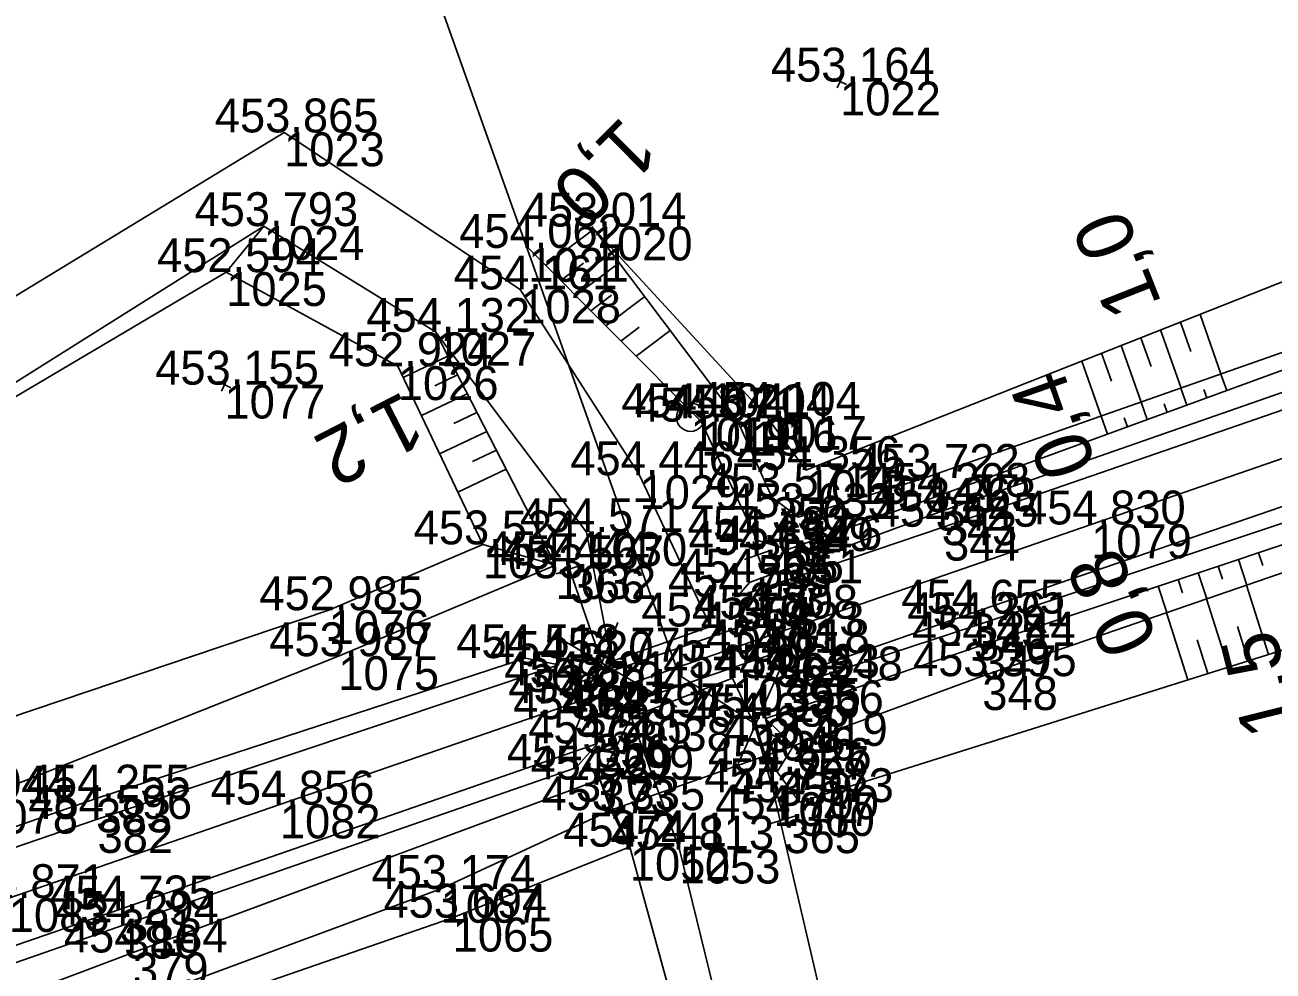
# Model space of a CAD drawing. Extents: x -751615 to -750797, y -1114905 to -1114561.
# Drawn here: x -751550.15 to -751505.91, y -1114830.9 to -1114797.38 of the extents above; entities that cross this region are included whole.
import ezdxf

# ---------------------------------------------------------------- set-up
doc = ezdxf.new("R2010")
doc.units = 0
for name, color, linetype in [('Vrstva 1', 7, 'Continuous'), ('Vrstva 19', 7, 'Continuous'), ('Vrstva 4', 7, 'Continuous'), ('Vrstva 48', 7, 'Continuous'), ('Vrstva 49', 7, 'Continuous'), ('Vrstva 51', 7, 'Continuous'), ('Vrstva 53', 7, 'Continuous'), ('Vrstva 60', 7, 'Continuous'), ('Vrstva 61', 7, 'Continuous'), ('Vrstva 7', 7, 'Continuous')]:
    doc.layers.add(name, color=color, linetype=linetype)

msp = doc.modelspace()

# ---------------------------------------------------------------- linework, layer by layer
at = {"layer": 'Vrstva 1'}
msp.add_lwpolyline([(-751416.742, -1114782.09), (-751426.633, -1114785.503), (-751435.883, -1114788.699), (-751445.473, -1114792.007), (-751455.331, -1114795.406), (-751464.93, -1114798.717), (-751474.392, -1114801.982), (-751484.022, -1114805.308), (-751487.237, -1114806.416), (-751493.406, -1114808.538), (-751502.885, -1114811.809), (-751512.358, -1114815.079), (-751523.744, -1114819.014), (-751530.663, -1114821.401), (-751541.116, -1114825.002), (-751550.726, -1114828.317), (-751560.172, -1114831.578), (-751569.853, -1114834.918), (-751579.125, -1114838.113), (-751588.602, -1114841.381)], dxfattribs=at)
at = {"layer": 'Vrstva 19'}
msp.add_line((-751529.387, -1114825.203), (-751522.915, -1114822.926), dxfattribs=at)
at = {"layer": 'Vrstva 4'}
for p, q in [((-751527.056, -1114820.157), (-751542.756, -1114776.116)), ((-751530.372, -1114816.499), (-751531.318, -1114816.825)), ((-751530.845, -1114816.662), (-751529.698, -1114819.986)), ((-751529.133, -1114818.557), (-751530.828, -1114822.844)), ((-751527.046, -1114821.54), (-751531.024, -1114819.21)), ((-751524.869, -1114823.564), (-751523.009, -1114819.347)), ((-751526.838, -1114820.502), (-751522.955, -1114822.986)), ((-751523.233, -1114825.525), (-751524.249, -1114822.158)), ((-751523.712, -1114825.669), (-751522.754, -1114825.381))]:
    msp.add_line(p, q, dxfattribs=at)
for points in [[(-751187.894, -1114700.58), (-751206.028, -1114707.041), (-751231.235, -1114715.596), (-751249.544, -1114721.971), (-751267.723, -1114728.471), (-751285.298, -1114734.541), (-751305.686, -1114741.509), (-751323.628, -1114747.668), (-751344.164, -1114754.785), (-751362.443, -1114761.123), (-751382.646, -1114767.996), (-751419.827, -1114780.907), (-751439.841, -1114787.752), (-751459.648, -1114794.565), (-751479.262, -1114801.395), (-751499.563, -1114808.301), (-751517.656, -1114814.613), (-751524.467, -1114817.135), (-751524.911, -1114817.646)], [(-751186.455, -1114705.269), (-751204.57, -1114711.262), (-751229.26, -1114719.967), (-751248.511, -1114726.389), (-751266.031, -1114732.591), (-751283.828, -1114738.73), (-751304.211, -1114745.766), (-751322.374, -1114751.898), (-751342.612, -1114758.897), (-751360.965, -1114765.168), (-751381.114, -1114772.121), (-751418.537, -1114784.997), (-751438.613, -1114791.912), (-751458.172, -1114798.656), (-751477.814, -1114805.419), (-751497.901, -1114812.476), (-751516.513, -1114818.688), (-751522.385, -1114820.606), (-751523.195, -1114820.521)], [(-751205.795, -1114707.603), (-751230.97, -1114716.264), (-751249.417, -1114722.675), (-751267.451, -1114728.869), (-751285.106, -1114734.872), (-751305.56, -1114741.936), (-751323.346, -1114748.135), (-751343.956, -1114755.234), (-751362.406, -1114761.583), (-751382.455, -1114768.543), (-751419.68, -1114781.407), (-751439.787, -1114788.305), (-751459.372, -1114795.057), (-751479.147, -1114801.881), (-751499.337, -1114808.873), (-751517.572, -1114815.159), (-751524.911, -1114817.646)], [(-751204.677, -1114710.75), (-751229.564, -1114719.281), (-751248.527, -1114725.936), (-751266.247, -1114732.037), (-751284.071, -1114738.15), (-751304.213, -1114745.084), (-751322.473, -1114751.338), (-751342.638, -1114758.269), (-751361.135, -1114764.639), (-751381.339, -1114771.707), (-751418.714, -1114784.623), (-751438.728, -1114791.466), (-751458.255, -1114798.22), (-751477.955, -1114804.997), (-751498.184, -1114811.907), (-751516.629, -1114818.238), (-751523.195, -1114820.521)], [(-751523.97, -1114818.419), (-751523.556, -1114819.637), (-751530.39, -1114821.979), (-751530.802, -1114820.777), (-751523.97, -1114818.419)], [(-751531.222, -1114820.049), (-751532.411, -1114819.814), (-751547.631, -1114824.789), (-751568.7, -1114832.128), (-751588.868, -1114838.968)], [(-751531.222, -1114820.049), (-751547.578, -1114825.515), (-751568.497, -1114832.683), (-751588.528, -1114839.629)], [(-751529.854, -1114822.836), (-751546.799, -1114828.717), (-751567.35, -1114835.812), (-751587.5, -1114842.776)], [(-751529.854, -1114822.836), (-751530.62, -1114823.702), (-751546.636, -1114829.261), (-751567.254, -1114836.441), (-751587.282, -1114843.385)]]:
    msp.add_lwpolyline(points, dxfattribs=at)
at = {"layer": 'Vrstva 48'}
for p, q in [((-751531.696, -1114805.9), (-751529.991, -1114804.613)), ((-751531.162, -1114806.436), (-751530.35, -1114805.824)), ((-751530.628, -1114806.973), (-751529.087, -1114805.81)), ((-751530.093, -1114807.509), (-751529.364, -1114806.959)), ((-751529.559, -1114808.046), (-751528.183, -1114807.007)), ((-751508.499, -1114807.637), (-751507.758, -1114809.748)), ((-751529.025, -1114808.582), (-751528.378, -1114808.094)), ((-751528.491, -1114809.119), (-751527.279, -1114808.204)), ((-751509.895, -1114808.189), (-751509.173, -1114810.245)), ((-751509.197, -1114807.913), (-751508.831, -1114808.955)), ((-751510.593, -1114808.464), (-751510.237, -1114809.479)), ((-751511.99, -1114809.016), (-751511.643, -1114810.003)), ((-751511.291, -1114808.74), (-751510.589, -1114810.742)), ((-751535.159, -1114809.114), (-751536.744, -1114809.871)), ((-751512.688, -1114809.291), (-751512.004, -1114811.239)), ((-751534.816, -1114809.781), (-751535.618, -1114810.164)), ((-751507.553, -1114810.336), (-751507.759, -1114809.749)), ((-751508.962, -1114810.85), (-751509.174, -1114810.246)), ((-751508.257, -1114810.593), (-751508.362, -1114810.295)), ((-751534.472, -1114810.448), (-751536.098, -1114811.224)), ((-751510.371, -1114811.365), (-751510.59, -1114810.743)), ((-751509.667, -1114811.107), (-751509.774, -1114810.801)), ((-751534.129, -1114811.116), (-751534.952, -1114811.508)), ((-751511.78, -1114811.879), (-751512.005, -1114811.239)), ((-751511.076, -1114811.622), (-751511.186, -1114811.306)), ((-751533.785, -1114811.783), (-751535.452, -1114812.578)), ((-751533.442, -1114812.45), (-751534.286, -1114812.852)), ((-751533.099, -1114813.117), (-751534.806, -1114813.932)), ((-751506.43, -1114816.082), (-751506.279, -1114816.533)), ((-751507.852, -1114816.558), (-751507.7, -1114817.015)), ((-751507.141, -1114816.32), (-751506.838, -1114817.227)), ((-751509.275, -1114817.033), (-751509.12, -1114817.496)), ((-751508.564, -1114816.795), (-751508.257, -1114817.715)), ((-751509.987, -1114817.271), (-751509.675, -1114818.203)), ((-751506.074, -1114819.687), (-751506.847, -1114817.231)), ((-751507.505, -1114820.137), (-751508.266, -1114817.719)), ((-751508.936, -1114820.587), (-751509.685, -1114818.207)), ((-751506.79, -1114819.912), (-751507.173, -1114818.693)), ((-751508.221, -1114820.362), (-751508.598, -1114819.162))]:
    msp.add_line(p, q, dxfattribs=at)
at = {"layer": 'Vrstva 49'}
for p, q in [((-751521.033, -1114799.496), (-751521.483, -1114799.278)), ((-751521.149, -1114799.162), (-751521.367, -1114799.612)), ((-751541.69, -1114804.508), (-751543.018, -1114806.139)), ((-751542.969, -1114809.901), (-751543.189, -1114810.351)), ((-751542.854, -1114810.236), (-751543.304, -1114810.016)), ((-751533.922, -1114815.785), (-751531.347, -1114816.521)), ((-751529.778, -1114824.115), (-751528.668, -1114821.908)), ((-751523.899, -1114821.949), (-751523.488, -1114823.845)), ((-751522.915, -1114822.926), (-751523.488, -1114823.845)), ((-751529.387, -1114825.203), (-751529.778, -1114824.115)), ((-751529.387, -1114825.203), (-751535.416, -1114827.991)), ((-751529.387, -1114825.203), (-751528.71, -1114826.495)), ((-751528.71, -1114826.495), (-751534.993, -1114829.012)), ((-751534.993, -1114829.012), (-751582.438, -1114845.392))]:
    msp.add_line(p, q, dxfattribs=at)
for points in [[(-751234.949, -1114713.279), (-751245.481, -1114717.135), (-751281.469, -1114726.527), (-751304.183, -1114733.326), (-751349.012, -1114749.456), (-751398.203, -1114766.871), (-751445.795, -1114779.905), (-751491.917, -1114801.089), (-751522.469, -1114813.154), (-751523.879, -1114811.232), (-751530.057, -1114804.525)], [(-751231.525, -1114714.481), (-751249.638, -1114721.458), (-751267.891, -1114727.816), (-751285.514, -1114733.952), (-751305.908, -1114740.796), (-751324.002, -1114747.035), (-751344.265, -1114754.112), (-751362.586, -1114760.516), (-751382.595, -1114767.438), (-751402.409, -1114774.045), (-751420.234, -1114780.2), (-751439.893, -1114787.152), (-751459.921, -1114794.045), (-751479.467, -1114800.491), (-751499.785, -1114807.5), (-751517.869, -1114814.102), (-751523.111, -1114815.97), (-751524.209, -1114815.639), (-751526.184, -1114811.436)], [(-751244.9, -1114718.575), (-751249.937, -1114720.628), (-751268.48, -1114726.929), (-751276.661, -1114729.623), (-751285.758, -1114733.326), (-751305.984, -1114740.165), (-751324.128, -1114746.656), (-751344.388, -1114753.731), (-751362.684, -1114760.234), (-751382.771, -1114766.903), (-751402.562, -1114773.563), (-751420.499, -1114779.462), (-751440.12, -1114786.635), (-751460.286, -1114793.369), (-751479.705, -1114799.993), (-751499.94, -1114807.004), (-751518.245, -1114813.43), (-751522.739, -1114814.822), (-751523.674, -1114814.114), (-751524.925, -1114811.322)], [(-751523.899, -1114821.949), (-751516.26, -1114819.366), (-751497.387, -1114813.062), (-751477.616, -1114806.13), (-751458.015, -1114799.124), (-751438.432, -1114792.474), (-751418.478, -1114785.506), (-751400.555, -1114779.532), (-751380.096, -1114772.486), (-751360.669, -1114765.898), (-751342.469, -1114759.505), (-751322.286, -1114752.456), (-751304.11, -1114746.299), (-751283.779, -1114739.207), (-751265.74, -1114733.22), (-751248.287, -1114727.037), (-751240.07, -1114724.297)], [(-751240.236, -1114725.654), (-751248.02, -1114728.046), (-751265.488, -1114734.037), (-751283.474, -1114739.989), (-751303.76, -1114746.769), (-751322.174, -1114753.101), (-751342.488, -1114759.998), (-751360.52, -1114766.361), (-751379.963, -1114773.044), (-751400.343, -1114780.093), (-751418.294, -1114786.259), (-751438.171, -1114793.174), (-751457.682, -1114799.957), (-751477.222, -1114807.057), (-751497.375, -1114813.972), (-751516.217, -1114820.454), (-751522.915, -1114822.926), (-751523.899, -1114821.949)], [(-751535.601, -1114808.255), (-751541.69, -1114804.508), (-751564.092, -1114818.587)], [(-751524.925, -1114811.322), (-751530.057, -1114804.525)], [(-751526.184, -1114811.436), (-751532.312, -1114805.281)], [(-751564.092, -1114818.587), (-751543.018, -1114806.139), (-751536.934, -1114809.473), (-751533.922, -1114815.785), (-751539.386, -1114818.117), (-751585.925, -1114833.806), (-751595.742, -1114835.716)], [(-751535.601, -1114808.255), (-751531.347, -1114816.521), (-751539.042, -1114819.748), (-751551.843, -1114824.829), (-751553.747, -1114826.383), (-751585.03, -1114836.593)], [(-751523.488, -1114823.845), (-751522.702, -1114824.917), (-751482.539, -1114812.284)], [(-751530.15, -1114844.167), (-751525.058, -1114839.997), (-751525.116, -1114834.058), (-751526.946, -1114826.6), (-751528.668, -1114821.908)], [(-751586.983, -1114844.483), (-751566.691, -1114837.92), (-751546.322, -1114830.244), (-751529.778, -1114824.115), (-751528.71, -1114826.495)], [(-751528.71, -1114826.495), (-751526.464, -1114834.679), (-751528.189, -1114839.231), (-751530.635, -1114842.817)], [(-751535.416, -1114827.991), (-751582.438, -1114845.392)]]:
    msp.add_lwpolyline(points, dxfattribs=at)
at = {"layer": 'Vrstva 51'}
for points in [[(-751609.483, -1114825.691), (-751605.933, -1114829.205), (-751594.773, -1114830.558), (-751581.97, -1114826.747), (-751566.399, -1114816.669), (-751540.967, -1114801.189), (-751532.595, -1114806.752), (-751528.368, -1114813.336), (-751525.848, -1114818.694), (-751529.358, -1114819.936), (-751530.249, -1114815.352), (-751535.601, -1114808.255), (-751541.69, -1114804.508), (-751564.092, -1114818.587), (-751580.945, -1114829.238), (-751594.664, -1114833.383), (-751607.051, -1114832.427), (-751612.458, -1114827.357)], [(-751519.201, -1114843.506), (-751523.621, -1114824.567), (-751524.266, -1114822.243), (-751525.072, -1114820.521), (-751528.668, -1114821.908), (-751526.946, -1114826.6), (-751525.116, -1114834.058), (-751525.058, -1114839.997), (-751530.15, -1114844.167)]]:
    msp.add_lwpolyline(points, dxfattribs=at)
at = {"layer": 'Vrstva 53'}
msp.add_line((-751526.512, -1114811.265), (-751526.606, -1114811.297), dxfattribs=at)
msp.add_circle((-751526.559, -1114811.281), 0.499, dxfattribs=at)
at = {"layer": 'Vrstva 60'}
for p, q in [((-751521.258, -1114799.387), (-751521.258, -1114799.387)), ((-751540.967, -1114801.189), (-751540.967, -1114801.189)), ((-751541.69, -1114804.508), (-751541.69, -1114804.508)), ((-751530.057, -1114804.525), (-751530.057, -1114804.525)), ((-751532.312, -1114805.281), (-751532.312, -1114805.281)), ((-751543.018, -1114806.139), (-751543.018, -1114806.139)), ((-751532.595, -1114806.752), (-751532.595, -1114806.752)), ((-751535.601, -1114808.255), (-751535.601, -1114808.255)), ((-751536.934, -1114809.473), (-751536.934, -1114809.473)), ((-751543.079, -1114810.126), (-751543.079, -1114810.126)), ((-751526.559, -1114811.281), (-751526.559, -1114811.281)), ((-751523.879, -1114811.232), (-751523.879, -1114811.232)), ((-751526.184, -1114811.436), (-751526.184, -1114811.436)), ((-751524.925, -1114811.322), (-751524.925, -1114811.322)), ((-751528.368, -1114813.336), (-751528.368, -1114813.336)), ((-751522.469, -1114813.154), (-751522.469, -1114813.154)), ((-751518.245, -1114813.43), (-751518.245, -1114813.43)), ((-751523.674, -1114814.114), (-751523.674, -1114814.114)), ((-751517.869, -1114814.102), (-751517.869, -1114814.102)), ((-751522.739, -1114814.822), (-751522.739, -1114814.822)), ((-751517.656, -1114814.613), (-751517.656, -1114814.613)), ((-751517.572, -1114815.159), (-751517.572, -1114815.159)), ((-751512.358, -1114815.079), (-751512.358, -1114815.079)), ((-751530.249, -1114815.352), (-751530.249, -1114815.352)), ((-751524.209, -1114815.639), (-751524.209, -1114815.639)), ((-751533.922, -1114815.785), (-751533.922, -1114815.785)), ((-751524.172, -1114816.157), (-751524.172, -1114816.157)), ((-751523.111, -1114815.97), (-751523.111, -1114815.97)), ((-751531.347, -1114816.521), (-751531.347, -1114816.521)), ((-751530.845, -1114816.662), (-751530.845, -1114816.662)), ((-751524.467, -1114817.135), (-751524.467, -1114817.135)), ((-751524.911, -1114817.646), (-751524.911, -1114817.646)), ((-751539.386, -1114818.117), (-751539.386, -1114818.117)), ((-751516.629, -1114818.238), (-751516.629, -1114818.238)), ((-751525.848, -1114818.694), (-751525.848, -1114818.694)), ((-751523.97, -1114818.419), (-751523.97, -1114818.419)), ((-751516.513, -1114818.688), (-751516.513, -1114818.688)), ((-751523.744, -1114819.014), (-751523.744, -1114819.014)), ((-751523.556, -1114819.637), (-751523.556, -1114819.637)), ((-751516.26, -1114819.366), (-751516.26, -1114819.366)), ((-751539.042, -1114819.748), (-751539.042, -1114819.748)), ((-751532.411, -1114819.814), (-751532.411, -1114819.814)), ((-751531.222, -1114820.049), (-751531.222, -1114820.049)), ((-751529.358, -1114819.936), (-751529.358, -1114819.936)), ((-751525.072, -1114820.521), (-751525.072, -1114820.521)), ((-751523.195, -1114820.521), (-751523.195, -1114820.521)), ((-751516.217, -1114820.454), (-751516.217, -1114820.454)), ((-751530.802, -1114820.777), (-751530.802, -1114820.777)), ((-751522.385, -1114820.606), (-751522.385, -1114820.606)), ((-751530.663, -1114821.401), (-751530.663, -1114821.401)), ((-751528.668, -1114821.908), (-751528.668, -1114821.908)), ((-751530.39, -1114821.979), (-751530.39, -1114821.979)), ((-751524.266, -1114822.243), (-751524.266, -1114822.243)), ((-751523.899, -1114821.949), (-751523.899, -1114821.949)), ((-751529.854, -1114822.836), (-751529.854, -1114822.836)), ((-751522.915, -1114822.926), (-751522.915, -1114822.926)), ((-751530.62, -1114823.702), (-751530.62, -1114823.702)), ((-751529.778, -1114824.115), (-751529.778, -1114824.115)), ((-751523.488, -1114823.845), (-751523.488, -1114823.845)), ((-751523.621, -1114824.567), (-751523.621, -1114824.567)), ((-751547.631, -1114824.789), (-751547.631, -1114824.789)), ((-751541.116, -1114825.002), (-751541.116, -1114825.002)), ((-751522.702, -1114824.917), (-751522.702, -1114824.917)), ((-751529.387, -1114825.203), (-751529.387, -1114825.203)), ((-751547.578, -1114825.515), (-751547.578, -1114825.515)), ((-751523.233, -1114825.525), (-751523.233, -1114825.525)), ((-751528.71, -1114826.495), (-751528.71, -1114826.495)), ((-751526.946, -1114826.6), (-751526.946, -1114826.6)), ((-751535.416, -1114827.991), (-751535.416, -1114827.991)), ((-751546.799, -1114828.717), (-751546.799, -1114828.717)), ((-751546.636, -1114829.261), (-751546.636, -1114829.261)), ((-751534.993, -1114829.012), (-751534.993, -1114829.012)), ((-751546.322, -1114830.244), (-751546.322, -1114830.244))]:
    msp.add_line(p, q, dxfattribs=at)
at = {"layer": 'Vrstva 7'}
for p, q in [((-751524.009, -1114816.63), (-751524.335, -1114815.684)), ((-751523.699, -1114815.994), (-751524.645, -1114816.32))]:
    msp.add_line(p, q, dxfattribs=at)

# ---------------------------------------------------------------- texts
at = {"layer": 'Vrstva 48'}
for s, rotation, p in [('1,0', 224.8741, (-751528.973, -1114800.562)), ('1,0', 111.5491, (-751509.843, -1114807.262)), ('0,4', 109.3437, (-751512.154, -1114813.015)), ('1,2', 207.2321, (-751536.722, -1114810.335)), ('0,8', 113.4705, (-751509.97, -1114819.186)), ('1,5', 103.9842, (-751504.972, -1114822.317))]:
    msp.add_text(s, height=2, rotation=rotation, dxfattribs=at).set_placement(p)
at = {"layer": 'Vrstva 60'}
for s, p in [('1022', (-751521.258, -1114800.587)), ('1023', (-751540.967, -1114802.389)), ('1024', (-751541.69, -1114805.708)), ('1020', (-751530.057, -1114805.725)), ('1021', (-751532.312, -1114806.481)), ('1025', (-751543.018, -1114807.339)), ('1028', (-751532.595, -1114807.952)), ('1027', (-751535.601, -1114809.455)), ('1026', (-751536.934, -1114810.673)), ('1077', (-751543.079, -1114811.326)), ('1019', (-751526.559, -1114812.481)), ('1016', (-751524.925, -1114812.522)), ('1017', (-751523.879, -1114812.432)), ('1018', (-751526.184, -1114812.636)), ('1029', (-751528.368, -1114814.536)), ('1013', (-751522.469, -1114814.354)), ('341', (-751518.245, -1114814.63)), ('350', (-751523.674, -1114815.314)), ('342', (-751517.869, -1114815.302)), ('349', (-751522.739, -1114816.022)), ('343', (-751517.656, -1114815.813)), ('344', (-751517.572, -1114816.359)), ('1079', (-751512.358, -1114816.279)), ('1030', (-751530.249, -1114816.552)), ('352', (-751524.209, -1114816.839)), ('1033', (-751533.922, -1114816.985)), ('535', (-751524.172, -1114817.357)), ('351', (-751523.111, -1114817.17)), ('1032', (-751531.347, -1114817.721)), ('366', (-751530.845, -1114817.862)), ('353', (-751524.467, -1114818.335)), ('354', (-751524.911, -1114818.846)), ('1076', (-751539.386, -1114819.317)), ('345', (-751516.629, -1114819.438)), ('1040', (-751525.848, -1114819.894)), ('361', (-751523.97, -1114819.619)), ('346', (-751516.513, -1114819.888)), ('371', (-751523.744, -1114820.214)), ('362', (-751523.556, -1114820.837)), ('347', (-751516.26, -1114820.566)), ('1075', (-751539.042, -1114820.948)), ('368', (-751532.411, -1114821.014)), ('367', (-751531.222, -1114821.249)), ('1041', (-751529.358, -1114821.136)), ('1039', (-751525.072, -1114821.721)), ('355', (-751523.195, -1114821.721)), ('356', (-751522.385, -1114821.806)), ('348', (-751516.217, -1114821.654)), ('364', (-751530.802, -1114821.977)), ('372', (-751530.663, -1114822.601)), ('1038', (-751528.668, -1114823.108)), ('358', (-751523.899, -1114823.149)), ('363', (-751530.39, -1114823.179)), ('1046', (-751524.266, -1114823.443)), ('369', (-751529.854, -1114824.036)), ('357', (-751522.915, -1114824.126)), ('370', (-751530.62, -1114824.902)), ('373', (-751529.778, -1114825.315)), ('359', (-751523.488, -1114825.045)), ('1047', (-751523.621, -1114825.767)), ('1078', (-751551.843, -1114826.029)), ('383', (-751547.631, -1114825.989)), ('1082', (-751541.116, -1114826.202)), ('360', (-751522.702, -1114826.117)), ('374', (-751529.387, -1114826.403)), ('382', (-751547.578, -1114826.715)), ('365', (-751523.233, -1114826.725)), ('1052', (-751528.71, -1114827.695)), ('1053', (-751526.946, -1114827.8)), ('1067', (-751535.416, -1114829.191)), ('1083', (-751550.726, -1114829.517)), ('381', (-751546.799, -1114829.917)), ('1065', (-751534.993, -1114830.212)), ('380', (-751546.636, -1114830.461)), ('379', (-751546.322, -1114831.444))]:
    msp.add_text(s, height=1.2, dxfattribs=at).set_placement(p)
at = {"layer": 'Vrstva 61'}
for s, p in [('453.164', (-751523.709, -1114799.387)), ('453.865', (-751543.423, -1114801.189)), ('453.793', (-751544.142, -1114804.508)), ('453.014', (-751532.508, -1114804.525)), ('454.062', (-751534.76, -1114805.281)), ('452.594', (-751545.469, -1114806.139)), ('454.161', (-751534.952, -1114806.752)), ('454.132', (-751538.049, -1114808.255)), ('452.924', (-751539.385, -1114809.473)), ('453.155', (-751545.535, -1114810.126)), ('454.104', (-751529.01, -1114811.281)), ('454.071', (-751528.541, -1114811.436)), ('453.204', (-751527.376, -1114811.322)), ('454.104', (-751526.33, -1114811.232)), ('454.446', (-751530.82, -1114813.336)), ('454.356', (-751524.921, -1114813.154)), ('453.722', (-751520.693, -1114813.43)), ('453.571', (-751526.031, -1114814.114)), ('454.208', (-751520.323, -1114814.102)), ('454.263', (-751520.108, -1114814.613)), ('453.633', (-751525.191, -1114814.822)), ('454.645', (-751520.028, -1114815.159)), ('454.830', (-751514.809, -1114815.079)), ('454.571', (-751532.606, -1114815.352)), ('453.524', (-751536.373, -1114815.785)), ('454.482', (-751526.657, -1114815.639)), ('454.376', (-751525.563, -1114815.97)), ('454.654', (-751526.623, -1114816.157)), ('454.444', (-751533.798, -1114816.521)), ('454.567', (-751533.297, -1114816.662)), ('454.485', (-751526.923, -1114817.135)), ('454.733', (-751527.363, -1114817.646)), ('452.985', (-751541.842, -1114818.117)), ('454.655', (-751519.085, -1114818.238)), ('454.770', (-751528.299, -1114818.694)), ('454.808', (-751526.424, -1114818.419)), ('454.261', (-751518.87, -1114818.688)), ('454.823', (-751526.196, -1114819.014)), ('454.244', (-751518.711, -1114819.366)), ('453.987', (-751541.494, -1114819.748)), ('454.518', (-751534.865, -1114819.814)), ('454.620', (-751533.673, -1114820.049)), ('454.775', (-751531.814, -1114819.936)), ('454.818', (-751526.01, -1114819.637)), ('453.395', (-751518.673, -1114820.454)), ('454.821', (-751533.159, -1114820.777)), ('454.805', (-751527.528, -1114820.521)), ('454.663', (-751525.647, -1114820.521)), ('454.348', (-751524.839, -1114820.606)), ('454.831', (-751533.02, -1114821.401)), ('454.825', (-751532.846, -1114821.979)), ('454.797', (-751531.12, -1114821.908)), ('454.685', (-751526.722, -1114822.243)), ('454.336', (-751526.351, -1114821.949)), ('454.565', (-751532.31, -1114822.836)), ('453.419', (-751525.369, -1114822.926)), ('454.356', (-751533.072, -1114823.702)), ('454.626', (-751525.94, -1114823.845)), ('454.299', (-751532.232, -1114824.115)), ('454.044', (-751554.294, -1114824.829)), ('454.255', (-751550.087, -1114824.789)), ('454.758', (-751526.075, -1114824.567)), ('454.573', (-751525.154, -1114824.917)), ('454.856', (-751543.568, -1114825.002)), ('453.335', (-751531.843, -1114825.203)), ('454.596', (-751550.03, -1114825.515)), ('454.700', (-751525.684, -1114825.525)), ('454.241', (-751531.067, -1114826.495)), ('454.813', (-751529.398, -1114826.6)), ('453.174', (-751537.867, -1114827.991)), ('454.871', (-751553.083, -1114828.317)), ('454.735', (-751549.255, -1114828.717)), ('454.294', (-751549.087, -1114829.261)), ('453.694', (-751537.444, -1114829.012)), ('454.184', (-751548.773, -1114830.244))]:
    msp.add_text(s, height=1.2, dxfattribs=at).set_placement(p)

doc.saveas('drawing.dxf')
